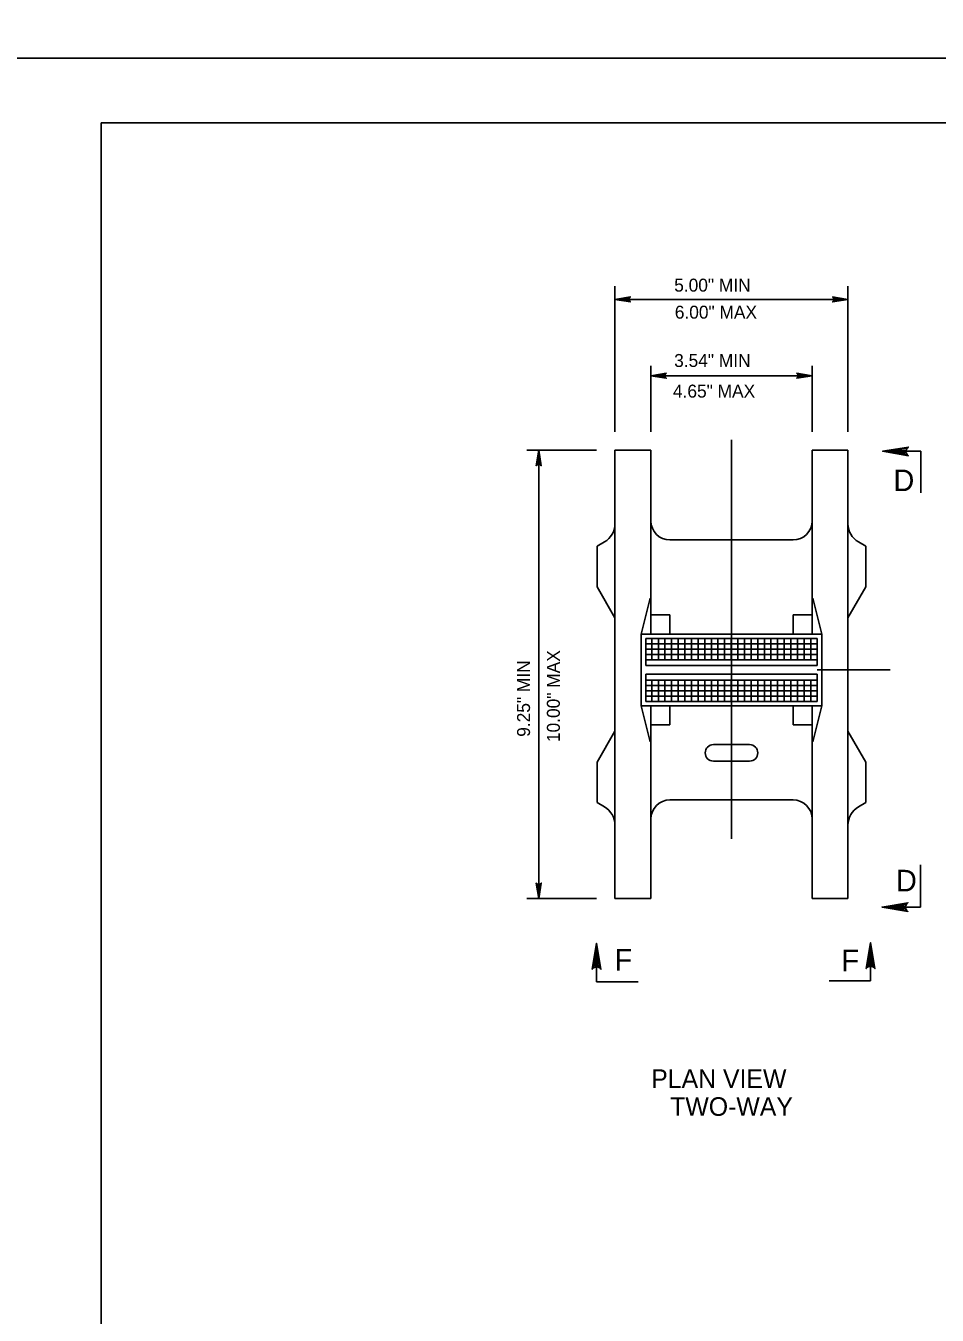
# Model space of a CAD drawing. Extents: x 639362 to 641108, y 298458 to 299646.
# Drawn here: x 640225.9 to 640436.9, y 298760.6 to 299059.1 of the extents above; entities that cross this region are included whole.
import ezdxf

# ---------------------------------------------------------------- set-up
doc = ezdxf.new("R2010")
doc.units = 0
for name, color, linetype in [('1', 7, 'Continuous'), ('2', 7, 'Continuous'), ('3', 7, 'Continuous'), ('PLT-BNDY', 7, 'Continuous')]:
    doc.layers.add(name, color=color, linetype=linetype)

# ---------------------------------------------------------------- blocks, each defined once
blk = doc.blocks.new('RARROW')
at = {"layer": '3'}
blk.add_lwpolyline([(-2.2695, 0.285), (-2.184875, 0.12075), (0, 0), (-2.2695, 0.285), (-2.38575, 0.384625), (0, 0), (-2.183125, -0.108), (-2.262875, -0.2705), (0, 0), (-2.38575, -0.379125), (-2.262875, -0.2705)], dxfattribs=at)

msp = doc.modelspace()

# ---------------------------------------------------------------- linework, layer by layer
at = {"layer": '1'}
for q in [(641029.31, 299036.63), (640243.31, 298472.63)]:
    msp.add_line((640243.31, 299036.63), q, dxfattribs=at)
at = {"layer": '2'}
for p, q in [((640362.29, 298965.15), (640362.29, 298998.87)), ((640416.24, 298965.15), (640416.24, 298998.87)), ((640416.24, 298995.79), (640362.29, 298995.79)), ((640370.59, 298965.15), (640370.59, 298980.4)), ((640407.94, 298978.12), (640370.59, 298978.12)), ((640407.94, 298965.15), (640407.94, 298980.4)), ((640389.27, 298963.3), (640389.27, 298870.92)), ((640357.99, 298960.85), (640341.84, 298960.85)), ((640344.63, 298960.85), (640344.63, 298857.09)), ((640362.29, 298960.85), (640362.29, 298857.09)), ((640362.29, 298960.85), (640370.59, 298960.85)), ((640370.59, 298960.85), (640370.59, 298918.31)), ((640407.94, 298960.85), (640416.24, 298960.85)), ((640407.94, 298960.85), (640407.94, 298918.31)), ((640416.24, 298960.85), (640416.24, 298857.09)), ((640433.12, 298960.62), (640424.24, 298960.62)), ((640433.12, 298951), (640433.12, 298960.62)), ((640359.85, 298939.63), (640358.14, 298938.65)), ((640403.52, 298940.1), (640375.02, 298940.1)), ((640418.68, 298939.64), (640420.4, 298938.65)), ((640358.14, 298929.29), (640358.14, 298938.65)), ((640420.4, 298929.29), (640420.4, 298938.65)), ((640358.14, 298929.29), (640362.29, 298922.1)), ((640420.4, 298929.29), (640416.24, 298922.1)), ((640368.34, 298918.31), (640370.46, 298926.65)), ((640410.2, 298918.31), (640408.08, 298926.65)), ((640375.02, 298922.74), (640370.59, 298922.74)), ((640375.02, 298918.31), (640375.02, 298922.74)), ((640403.52, 298918.31), (640403.52, 298922.74)), ((640407.94, 298922.74), (640403.52, 298922.74)), ((640410.2, 298918.31), (640368.34, 298918.31)), ((640368.34, 298910.01), (640368.34, 298918.31)), ((640410.2, 298910.01), (640410.2, 298918.31)), ((640369.4, 298911.01), (640369.4, 298917.31)), ((640409.14, 298917.31), (640369.4, 298917.31)), ((640409.14, 298916.07), (640369.4, 298916.07)), ((640409.14, 298914.82), (640369.4, 298914.82)), ((640370.8, 298912.33), (640370.8, 298917.31)), ((640372.34, 298912.33), (640372.34, 298917.31)), ((640373.87, 298912.33), (640373.87, 298917.31)), ((640375.41, 298912.33), (640375.41, 298917.31)), ((640376.94, 298912.33), (640376.94, 298917.31)), ((640378.48, 298912.33), (640378.48, 298917.31)), ((640380.01, 298912.33), (640380.01, 298917.31)), ((640381.54, 298912.33), (640381.54, 298917.31)), ((640383.07, 298912.33), (640383.07, 298917.31)), ((640384.61, 298912.33), (640384.61, 298917.31)), ((640386.14, 298912.33), (640386.14, 298917.31)), ((640387.67, 298912.33), (640387.67, 298917.31)), ((640389.21, 298912.33), (640389.21, 298917.31)), ((640390.74, 298912.33), (640390.74, 298917.31)), ((640392.27, 298912.33), (640392.27, 298917.31)), ((640393.81, 298912.33), (640393.81, 298917.31)), ((640395.34, 298912.33), (640395.34, 298917.31)), ((640396.88, 298912.33), (640396.88, 298917.31)), ((640398.41, 298912.33), (640398.41, 298917.31)), ((640399.94, 298912.33), (640399.94, 298917.31)), ((640401.48, 298912.33), (640401.48, 298917.31)), ((640403.01, 298912.33), (640403.01, 298917.31)), ((640404.54, 298912.33), (640404.54, 298917.31)), ((640406.08, 298912.33), (640406.08, 298917.31)), ((640407.61, 298912.33), (640407.61, 298917.31)), ((640409.14, 298911.01), (640409.14, 298917.31)), ((640409.14, 298913.58), (640369.4, 298913.58)), ((640409.14, 298912.33), (640369.4, 298912.33)), ((640368.34, 298910.01), (640368.34, 298901.71)), ((640409.14, 298911.01), (640369.4, 298911.01)), ((640409.14, 298909.01), (640369.4, 298909.01)), ((640369.4, 298909.01), (640369.4, 298902.7)), ((640409.14, 298910.01), (640425.99, 298910.01)), ((640409.14, 298909.01), (640409.14, 298902.7)), ((640410.2, 298910.01), (640410.2, 298901.71)), ((640409.14, 298907.68), (640369.4, 298907.68)), ((640409.14, 298906.44), (640369.4, 298906.44)), ((640370.8, 298907.68), (640370.8, 298902.7)), ((640372.34, 298907.68), (640372.34, 298902.7)), ((640373.87, 298907.68), (640373.87, 298902.7)), ((640375.41, 298907.68), (640375.41, 298902.7)), ((640376.94, 298907.68), (640376.94, 298902.7)), ((640378.48, 298907.68), (640378.48, 298902.7)), ((640380.01, 298907.68), (640380.01, 298902.7)), ((640381.54, 298907.68), (640381.54, 298902.7)), ((640383.07, 298907.68), (640383.07, 298902.7)), ((640384.61, 298907.68), (640384.61, 298902.7)), ((640386.14, 298907.68), (640386.14, 298902.7)), ((640387.67, 298907.68), (640387.67, 298902.7)), ((640389.21, 298907.68), (640389.21, 298902.7)), ((640390.74, 298907.68), (640390.74, 298902.7)), ((640392.27, 298907.68), (640392.27, 298902.7)), ((640393.81, 298907.68), (640393.81, 298902.7)), ((640395.34, 298907.68), (640395.34, 298902.7)), ((640396.88, 298907.68), (640396.88, 298902.7)), ((640398.41, 298907.68), (640398.41, 298902.7)), ((640399.94, 298907.68), (640399.94, 298902.7)), ((640401.48, 298907.68), (640401.48, 298902.7)), ((640403.01, 298907.68), (640403.01, 298902.7)), ((640404.54, 298907.68), (640404.54, 298902.7)), ((640406.08, 298907.68), (640406.08, 298902.7)), ((640407.61, 298907.68), (640407.61, 298902.7)), ((640409.14, 298905.2), (640369.4, 298905.2)), ((640409.14, 298903.95), (640369.4, 298903.95)), ((640410.2, 298901.71), (640368.34, 298901.71)), ((640368.34, 298901.71), (640370.46, 298893.37)), ((640409.14, 298902.7), (640369.4, 298902.7)), ((640370.59, 298901.71), (640370.59, 298857.09)), ((640375.02, 298901.71), (640375.02, 298897.28)), ((640403.52, 298901.71), (640403.52, 298897.28)), ((640407.94, 298901.71), (640407.94, 298857.09)), ((640410.2, 298901.71), (640408.08, 298893.37)), ((640375.02, 298897.28), (640370.59, 298897.28)), ((640407.94, 298897.28), (640403.52, 298897.28)), ((640358.14, 298888.65), (640362.29, 298895.84)), ((640420.4, 298888.65), (640416.24, 298895.84)), ((640385.09, 298892.72), (640393.45, 298892.72)), ((640358.14, 298888.65), (640358.14, 298879.3)), ((640385.09, 298888.9), (640393.45, 298888.9)), ((640420.4, 298888.65), (640420.4, 298879.3)), ((640359.85, 298878.31), (640358.14, 298879.3)), ((640375.02, 298879.92), (640403.52, 298879.92)), ((640418.68, 298878.31), (640420.4, 298879.3)), ((640433, 298864.87), (640433, 298855.12)), ((640357.99, 298857.09), (640341.84, 298857.09)), ((640362.29, 298857.09), (640370.59, 298857.09)), ((640416.24, 298857.09), (640407.94, 298857.09)), ((640433, 298855.12), (640424.12, 298855.12)), ((640358.03, 298837.85), (640358.03, 298846.73)), ((640421.48, 298838.01), (640421.48, 298846.88)), ((640367.65, 298837.85), (640358.03, 298837.85)), ((640411.85, 298838.01), (640421.48, 298838.01))]:
    msp.add_line(p, q, dxfattribs=at)
for points in [[(640365.7, 298995.37), (640365.57, 298995.61), (640362.29, 298995.79), (640365.7, 298995.37), (640365.87, 298995.22), (640362.29, 298995.79), (640365.56, 298995.96), (640365.68, 298996.2), (640362.29, 298995.79), (640365.87, 298996.36), (640365.68, 298996.2)], [(640412.84, 298996.22), (640412.97, 298995.97), (640416.24, 298995.79), (640412.84, 298996.22), (640412.66, 298996.37), (640416.24, 298995.79), (640412.97, 298995.63), (640412.85, 298995.39), (640416.24, 298995.79), (640412.66, 298995.22), (640412.85, 298995.39)], [(640374, 298977.7), (640373.87, 298977.94), (640370.59, 298978.12), (640374, 298977.7), (640374.17, 298977.55), (640370.59, 298978.12), (640373.87, 298978.29), (640373.98, 298978.53), (640370.59, 298978.12), (640374.17, 298978.69), (640373.98, 298978.53)], [(640404.54, 298978.55), (640404.67, 298978.31), (640407.94, 298978.12), (640404.54, 298978.55), (640404.36, 298978.7), (640407.94, 298978.12), (640404.67, 298977.96), (640404.55, 298977.72), (640407.94, 298978.12), (640404.36, 298977.56), (640404.55, 298977.72)], [(640344.21, 298957.45), (640344.45, 298957.57), (640344.63, 298960.85), (640344.21, 298957.45), (640344.06, 298957.27), (640344.63, 298960.85), (640344.8, 298957.58), (640345.04, 298957.46), (640344.63, 298960.85), (640345.2, 298957.27), (640345.04, 298957.46)], [(640345.06, 298860.5), (640344.81, 298860.37), (640344.63, 298857.09), (640345.06, 298860.5), (640345.21, 298860.67), (640344.63, 298857.09), (640344.47, 298860.37), (640344.23, 298860.49), (640344.63, 298857.09), (640344.06, 298860.67), (640344.23, 298860.49)]]:
    msp.add_lwpolyline(points, dxfattribs=at)
for centre, radius, start, end in [((640357.42, 298943.85), 4.87, 300.0116, 0), ((640375.02, 298944.53), 4.43, 180, 270), ((640403.52, 298944.53), 4.43, 270, 0), ((640421.11, 298943.85), 4.87, 180, 239.9911), ((640385.09, 298890.81), 1.91, 90, 270), ((640393.45, 298890.81), 1.91, 270, 90), ((640375.02, 298875.49), 4.43, 90, 180), ((640403.52, 298875.49), 4.43, 0, 90), ((640357.42, 298874.09), 4.87, 0, 59.9884), ((640421.11, 298874.09), 4.87, 120.0089, 180)]:
    msp.add_arc(centre, radius, start, end, dxfattribs=at)
at = {"layer": 'PLT-BNDY'}
for points in [[(640203.31, 299645.63), (641044.31, 299645.63), (641044.31, 299051.63), (640203.31, 299051.63)], [(640203.31, 299051.63), (641044.31, 299051.63), (641044.31, 298457.63), (640203.31, 298457.63)]]:
    msp.add_lwpolyline(points, close=True, dxfattribs=at)

# ---------------------------------------------------------------- block references
at = {"layer": '2', "xscale": 2.5148695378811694}
for p, yscale, rotation in [((640424.24, 298960.62), 2.618592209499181, 180), ((640424.12, 298855.12), 2.618592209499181, 180), ((640358.03, 298846.73), -2.618592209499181, 90.00000000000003), ((640421.48, 298846.88), 2.618592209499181, 89.99999999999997)]:
    msp.add_blockref('RARROW', p, dxfattribs=dict(at, yscale=yscale, rotation=rotation))

# ---------------------------------------------------------------- texts
at = {"layer": '2'}
for s, height, p in [('5.00" MIN', 3, (640376, 298997.59)), ('6.00" MAX', 3, (640376.14, 298991.33)), ('3.54" MIN', 3, (640375.99, 298980.15)), ('4.65" MAX', 3, (640375.71, 298973.06)), ('D', 5, (640426.77, 298951.4)), ('D', 5, (640427.35, 298858.75)), ('F', 5, (640362.17, 298840.43)), ('F', 5, (640414.72, 298840.27)), ('PLAN VIEW', 4.3, (640370.68, 298813.25)), ('TWO-WAY', 4.3, (640375.07, 298806.8))]:
    msp.add_text(s, height=height, dxfattribs=at).set_placement(p)
for s, p in [('9.25" MIN', (640342.62, 298894.54)), ('10.00" MAX', (640349.52, 298893.31))]:
    msp.add_text(s, height=3, rotation=90, dxfattribs=at).set_placement(p)

doc.saveas('drawing.dxf')
